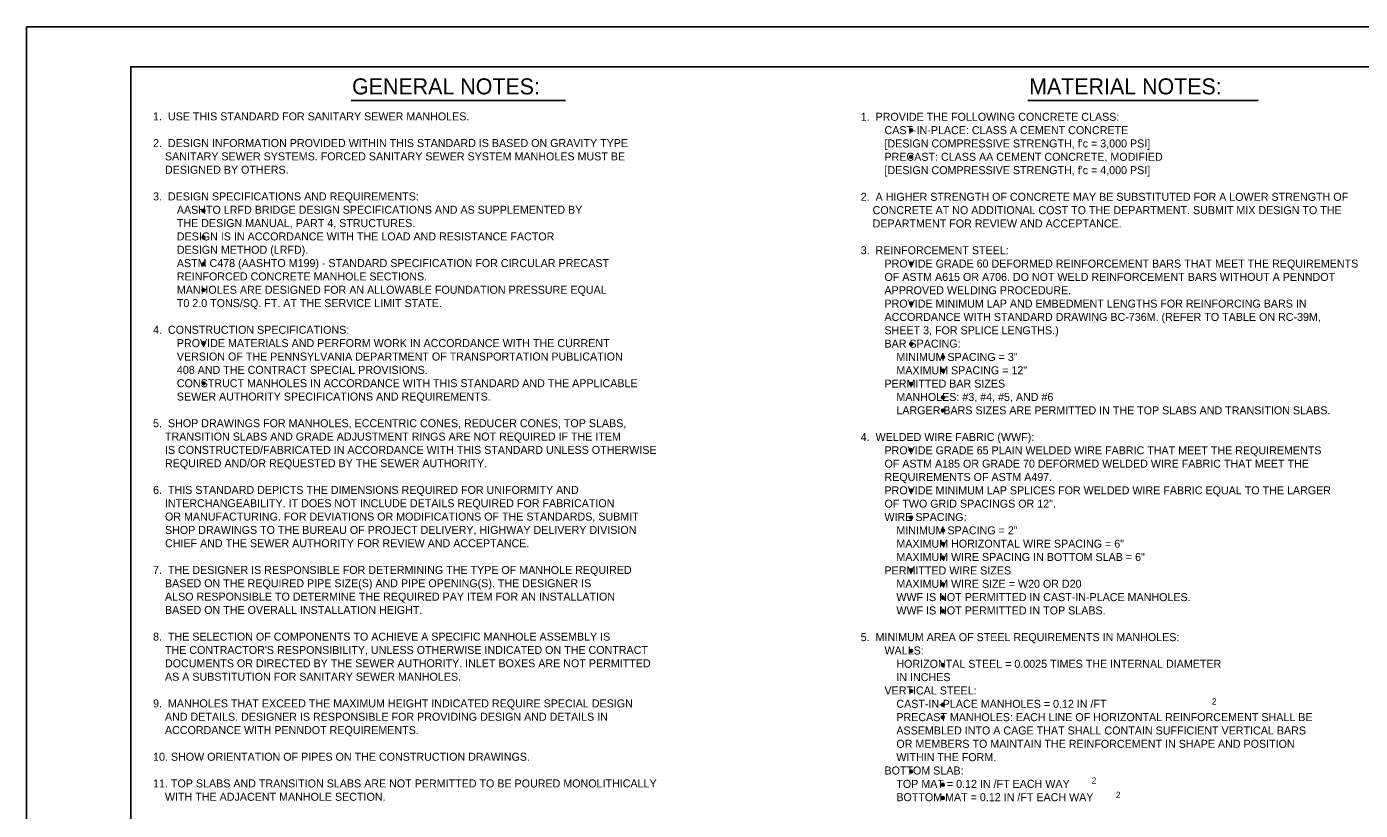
# Model space of a CAD drawing. Extents: x 2106427 to 2114911, y 988717 to 990787.
# Drawn here: x 2106427 to 2108067, y 989824 to 990787 of the extents above; entities that cross this region are included whole.
import ezdxf

# ---------------------------------------------------------------- set-up
doc = ezdxf.new("R2010")
doc.units = 0
for name, color, linetype in [('1', 7, 'Continuous'), ('3', 7, 'Continuous'), ('PLT-BNDY', 7, 'Continuous')]:
    doc.layers.add(name, color=color, linetype=linetype)

msp = doc.modelspace()

# ---------------------------------------------------------------- linework, layer by layer
at = {"layer": '1'}
for p, q in [((2106825.6, 990696.4), (2107089.5, 990696.4)), ((2107657.9, 990696.4), (2107941.3, 990696.4))]:
    msp.add_line(p, q, dxfattribs=at)
msp.add_lwpolyline([(2109133.2, 988887.7), (2109133.2, 990738.1), (2106554.5, 990738.1), (2106554.5, 988887.7), (2109133.2, 988887.7), (2109133.2, 988974.2), (2108477, 988974.2), (2108477, 989186.4), (2109133.2, 989186.4), (2109133.2, 989281.4), (2108477, 989281.4), (2108477, 988887.7), (2108735.6, 988887.7), (2108735.6, 988974.2), (2108735.6, 988887.7), (2108988.2, 988887.7), (2108988.2, 988974.2), (2108988.2, 988933.8), (2109133.2, 988933.8)], dxfattribs=at)
for centre, radius in [((2107514.6, 990659.9), 1.75), ((2107514.6, 990659.9), 1.31), ((2107514.6, 990659.9), 0.875), ((2107514.6, 990659.9), 0.437), ((2107514.6, 990627.2), 1.75), ((2107514.6, 990627.2), 1.31), ((2107514.6, 990627.2), 0.875), ((2107514.6, 990627.2), 0.437), ((2106644, 990561), 1.75), ((2106644, 990561), 1.31), ((2106644, 990561), 0.875), ((2106644, 990561), 0.437), ((2106644, 990528.3), 1.75), ((2106644, 990528.3), 1.31), ((2106644, 990528.3), 0.875), ((2106644, 990528.3), 0.437), ((2106644, 990495.4), 1.75), ((2106644, 990495.4), 1.31), ((2106644, 990495.4), 0.875), ((2106644, 990495.4), 0.437), ((2107514.6, 990496), 1.75), ((2107514.6, 990496), 1.31), ((2107514.6, 990496), 0.875), ((2107514.6, 990496), 0.437), ((2106644, 990463.5), 1.75), ((2106644, 990463.5), 1.31), ((2106644, 990463.5), 0.875), ((2106644, 990463.5), 0.437), ((2107514.6, 990447), 1.75), ((2107514.6, 990447), 1.31), ((2107514.6, 990447), 0.875), ((2107514.6, 990447), 0.437), ((2106644, 990398), 1.75), ((2106644, 990398), 1.31), ((2106644, 990398), 0.875), ((2106644, 990398), 0.437), ((2107514.6, 990397.2), 1.75), ((2107514.6, 990397.2), 1.31), ((2107514.6, 990397.2), 0.875), ((2107514.6, 990397.2), 0.437), ((2107553.7, 990380.8), 1.75), ((2107553.7, 990380.8), 1.31), ((2107553.7, 990380.8), 0.875), ((2107553.7, 990380.8), 0.437), ((2107553.7, 990364.4), 1.75), ((2107553.7, 990364.4), 1.31), ((2107553.7, 990364.4), 0.875), ((2107553.7, 990364.4), 0.437), ((2106644, 990348.8), 1.75), ((2106644, 990348.8), 1.31), ((2106644, 990348.8), 0.875), ((2106644, 990348.8), 0.437), ((2107514.6, 990348), 1.75), ((2107514.6, 990348), 1.31), ((2107514.6, 990348), 0.875), ((2107514.6, 990348), 0.437), ((2107553.7, 990331.5), 1.75), ((2107553.7, 990331.5), 1.31), ((2107553.7, 990331.5), 0.875), ((2107553.7, 990331.5), 0.437), ((2107553.7, 990315.4), 1.75), ((2107553.7, 990315.4), 1.31), ((2107553.7, 990315.4), 0.875), ((2107553.7, 990315.4), 0.437), ((2107513.8, 990266.9), 1.75), ((2107513.8, 990266.9), 1.31), ((2107513.8, 990266.9), 0.875), ((2107513.8, 990266.9), 0.437), ((2107514.6, 990217.1), 1.75), ((2107514.6, 990217.1), 1.31), ((2107514.6, 990217.1), 0.875), ((2107514.6, 990217.1), 0.437), ((2107514.5, 990183.7), 1.75), ((2107514.5, 990183.7), 1.31), ((2107514.5, 990183.7), 0.875), ((2107514.5, 990183.7), 0.437), ((2107553.7, 990168), 1.75), ((2107553.7, 990168), 1.31), ((2107553.7, 990168), 0.875), ((2107553.7, 990168), 0.437), ((2107553.7, 990151.5), 1.75), ((2107553.7, 990151.5), 1.31), ((2107553.7, 990151.5), 0.875), ((2107553.7, 990151.5), 0.437), ((2107553.7, 990134.4), 1.75), ((2107553.7, 990134.4), 1.31), ((2107553.7, 990134.4), 0.875), ((2107553.7, 990134.4), 0.437), ((2107514.5, 990118.9), 1.75), ((2107514.5, 990118.9), 1.31), ((2107514.5, 990118.9), 0.875), ((2107514.5, 990118.9), 0.437), ((2107553.6, 990101.6), 1.75), ((2107553.6, 990101.6), 1.31), ((2107553.6, 990101.6), 0.875), ((2107553.6, 990101.6), 0.437), ((2107553.6, 990085.2), 1.75), ((2107553.6, 990085.2), 1.31), ((2107553.6, 990085.2), 0.875), ((2107553.6, 990085.2), 0.437), ((2107553.6, 990068.5), 1.75), ((2107553.6, 990068.5), 1.31), ((2107553.6, 990068.5), 0.875), ((2107553.6, 990068.5), 0.437), ((2107514.5, 990019.9), 1.75), ((2107514.5, 990019.9), 1.31), ((2107514.5, 990019.9), 0.875), ((2107514.5, 990019.9), 0.437), ((2107553.6, 990002.5), 1.75), ((2107553.6, 990002.5), 1.31), ((2107553.6, 990002.5), 0.875), ((2107553.6, 990002.5), 0.437), ((2107514.5, 989970.2), 1.75), ((2107514.5, 989970.2), 1.31), ((2107514.5, 989970.2), 0.875), ((2107514.5, 989970.2), 0.437), ((2107553.6, 989953.6), 1.75), ((2107553.6, 989953.6), 1.31), ((2107553.6, 989953.6), 0.875), ((2107553.6, 989953.6), 0.437), ((2107553.6, 989938.2), 1.75), ((2107553.6, 989938.2), 1.31), ((2107553.6, 989938.2), 0.875), ((2107553.6, 989938.2), 0.437), ((2107514.5, 989871.4), 1.75), ((2107514.5, 989871.4), 1.31), ((2107514.5, 989871.4), 0.875), ((2107514.5, 989871.4), 0.437), ((2107553.6, 989855.3), 1.75), ((2107553.6, 989855.3), 1.31), ((2107553.6, 989855.3), 0.875), ((2107553.6, 989855.3), 0.437), ((2107553.6, 989838.9), 1.75), ((2107553.6, 989838.9), 1.31), ((2107553.6, 989838.9), 0.875), ((2107553.6, 989838.9), 0.437)]:
    msp.add_circle(centre, radius, dxfattribs=at)
at = {"layer": 'PLT-BNDY'}
msp.add_lwpolyline([(2106426.5, 990787.3), (2109185.7, 990787.3), (2109185.7, 988838.5), (2106426.5, 988838.5)], close=True, dxfattribs=at)

# ---------------------------------------------------------------- texts
at = {"layer": '3'}
for s, height, p in [('GENERAL NOTES:', 19.685, (2106826.8, 990704.1)), ('MATERIAL NOTES:', 19.685, (2107659.7, 990704.1)), ('1.  USE THIS STANDARD FOR SANITARY SEWER MANHOLES.', 9.843, (2106582, 990672.1)), ('1.  PROVIDE THE FOLLOWING CONCRETE CLASS:', 9.843, (2107452.5, 990671.6)), ('        CAST-IN-PLACE: CLASS A CEMENT CONCRETE', 9.843, (2107452.5, 990655.2)), ('2.  DESIGN INFORMATION PROVIDED WITHIN THIS STANDARD IS BASED ON GRAVITY TYPE', 9.843, (2106582, 990639.3)), ("        [DESIGN COMPRESSIVE STRENGTH, f'c = 3,000 PSI]", 9.843, (2107452.5, 990638.8)), ('    SANITARY SEWER SYSTEMS. FORCED SANITARY SEWER SYSTEM MANHOLES MUST BE', 9.843, (2106582, 990622.9)), ('        PRECAST: CLASS AA CEMENT CONCRETE, MODIFIED', 9.843, (2107452.5, 990622.4)), ('    DESIGNED BY OTHERS.', 9.843, (2106582, 990606.5)), ("        [DESIGN COMPRESSIVE STRENGTH, f'c = 4,000 PSI]", 9.843, (2107452.5, 990606)), ('3.  DESIGN SPECIFICATIONS AND REQUIREMENTS:', 9.843, (2106582, 990573.7)), ('2.  A HIGHER STRENGTH OF CONCRETE MAY BE SUBSTITUTED FOR A LOWER STRENGTH OF', 9.843, (2107452.5, 990573.2)), ('        AASHTO LRFD BRIDGE DESIGN SPECIFICATIONS AND AS SUPPLEMENTED BY', 9.843, (2106582, 990557.3)), ('    CONCRETE AT NO ADDITIONAL COST TO THE DEPARTMENT. SUBMIT MIX DESIGN TO THE', 9.843, (2107452.5, 990556.8)), ('        THE DESIGN MANUAL, PART 4, STRUCTURES.', 9.843, (2106582, 990540.9)), ('    DEPARTMENT FOR REVIEW AND ACCEPTANCE.', 9.843, (2107452.5, 990540.4)), ('        DESIGN IS IN ACCORDANCE WITH THE LOAD AND RESISTANCE FACTOR', 9.843, (2106582, 990524.5)), ('        DESIGN METHOD (LRFD).', 9.843, (2106582, 990508.1)), ('3.  REINFORCEMENT STEEL:', 9.843, (2107452.5, 990507.5)), ('        ASTM C478 (AASHTO M199) - STANDARD SPECIFICATION FOR CIRCULAR PRECAST', 9.843, (2106582, 990491.7)), ('        PROVIDE GRADE 60 DEFORMED REINFORCEMENT BARS THAT MEET THE REQUIREMENTS', 9.843, (2107452.5, 990491.1)), ('        REINFORCED CONCRETE MANHOLE SECTIONS.', 9.843, (2106582, 990475.3)), ('        OF ASTM A615 OR A706. DO NOT WELD REINFORCEMENT BARS WITHOUT A PENNDOT', 9.843, (2107452.5, 990474.7)), ('        MANHOLES ARE DESIGNED FOR AN ALLOWABLE FOUNDATION PRESSURE EQUAL', 9.843, (2106582, 990458.9)), ('        APPROVED WELDING PROCEDURE.', 9.843, (2107452.5, 990458.3)), ('        T0 2.0 TONS/SQ. FT. AT THE SERVICE LIMIT STATE.', 9.843, (2106582, 990442.5)), ('        PROVIDE MINIMUM LAP AND EMBEDMENT LENGTHS FOR REINFORCING BARS IN ', 9.843, (2107452.5, 990441.9)), ('        ACCORDANCE WITH STANDARD DRAWING BC-736M. (REFER TO TABLE ON RC-39M,', 9.843, (2107452.5, 990425.5)), ('4.  CONSTRUCTION SPECIFICATIONS:', 9.843, (2106582, 990409.7)), ('        SHEET 3, FOR SPLICE LENGTHS.)', 9.843, (2107452.5, 990409.1)), ('        PROVIDE MATERIALS AND PERFORM WORK IN ACCORDANCE WITH THE CURRENT', 9.843, (2106582, 990393.3)), ('        BAR SPACING:', 9.843, (2107452.5, 990392.7)), ('        VERSION OF THE PENNSYLVANIA DEPARTMENT OF TRANSPORTATION PUBLICATION', 9.843, (2106582, 990376.8)), ('            MINIMUM SPACING = 3"', 9.843, (2107452.5, 990376.3)), ('        408 AND THE CONTRACT SPECIAL PROVISIONS.', 9.843, (2106582, 990360.4)), ('            MAXIMUM SPACING = 12"', 9.843, (2107452.5, 990359.9)), ('        CONSTRUCT MANHOLES IN ACCORDANCE WITH THIS STANDARD AND THE APPLICABLE', 9.843, (2106582, 990344)), ('        PERMITTED BAR SIZES', 9.843, (2107452.5, 990343.5)), ('        SEWER AUTHORITY SPECIFICATIONS AND REQUIREMENTS.', 9.843, (2106582, 990327.6)), ('            MANHOLES: #3, #4, #5, AND #6', 9.843, (2107452.5, 990327.1)), ('            LARGER BARS SIZES ARE PERMITTED IN THE TOP SLABS AND TRANSITION SLABS.', 9.843, (2107452.5, 990310.7)), ('5.  SHOP DRAWINGS FOR MANHOLES, ECCENTRIC CONES, REDUCER CONES, TOP SLABS,', 9.843, (2106582, 990294.8)), ('    TRANSITION SLABS AND GRADE ADJUSTMENT RINGS ARE NOT REQUIRED IF THE ITEM', 9.843, (2106582, 990278.4)), ('4.  WELDED WIRE FABRIC (WWF):', 9.843, (2107452.5, 990277.9)), ('    IS CONSTRUCTED/FABRICATED IN ACCORDANCE WITH THIS STANDARD UNLESS OTHERWISE', 9.843, (2106582, 990262)), ('        PROVIDE GRADE 65 PLAIN WELDED WIRE FABRIC THAT MEET THE REQUIREMENTS', 9.843, (2107452.5, 990261.5)), ('    REQUIRED AND/OR REQUESTED BY THE SEWER AUTHORITY.', 9.843, (2106582, 990245.6)), ('        OF ASTM A185 OR GRADE 70 DEFORMED WELDED WIRE FABRIC THAT MEET THE', 9.843, (2107452.5, 990245.1)), ('        REQUIREMENTS OF ASTM A497.', 9.843, (2107452.5, 990228.7)), ('6.  THIS STANDARD DEPICTS THE DIMENSIONS REQUIRED FOR UNIFORMITY AND', 9.843, (2106582, 990212.8)), ('        PROVIDE MINIMUM LAP SPLICES FOR WELDED WIRE FABRIC EQUAL TO THE LARGER', 9.843, (2107452.5, 990212.3)), ('    INTERCHANGEABILITY. IT DOES NOT INCLUDE DETAILS REQUIRED FOR FABRICATION', 9.843, (2106582, 990196.4)), ('        OF TWO GRID SPACINGS OR 12".', 9.843, (2107452.5, 990195.9)), ('    OR MANUFACTURING. FOR DEVIATIONS OR MODIFICATIONS OF THE STANDARDS, SUBMIT', 9.843, (2106582, 990180)), ('        WIRE SPACING:', 9.843, (2107452.5, 990179.5)), ('    SHOP DRAWINGS TO THE BUREAU OF PROJECT DELIVERY, HIGHWAY DELIVERY DIVISION', 9.843, (2106582, 990163.6)), ('            MINIMUM SPACING = 2"', 9.843, (2107452.5, 990163.1)), ('    CHIEF AND THE SEWER AUTHORITY FOR REVIEW AND ACCEPTANCE.', 9.843, (2106582, 990147.2)), ('            MAXIMUM HORIZONTAL WIRE SPACING = 6" ', 9.843, (2107452.5, 990146.7)), ('            MAXIMUM WIRE SPACING IN BOTTOM SLAB = 6"', 9.843, (2107452.5, 990130.3)), ('7.  THE DESIGNER IS RESPONSIBLE FOR DETERMINING THE TYPE OF MANHOLE REQUIRED', 9.843, (2106582, 990114.4)), ('        PERMITTED WIRE SIZES', 9.843, (2107452.5, 990113.8)), ('    BASED ON THE REQUIRED PIPE SIZE(S) AND PIPE OPENING(S). THE DESIGNER IS', 9.843, (2106582, 990098)), ('            MAXIMUM WIRE SIZE = W20 OR D20', 9.843, (2107452.5, 990097.4)), ('    ALSO RESPONSIBLE TO DETERMINE THE REQUIRED PAY ITEM FOR AN INSTALLATION', 9.843, (2106582, 990081.6)), ('            WWF IS NOT PERMITTED IN CAST-IN-PLACE MANHOLES.', 9.843, (2107452.5, 990081)), ('    BASED ON THE OVERALL INSTALLATION HEIGHT.', 9.843, (2106582, 990065.2)), ('            WWF IS NOT PERMITTED IN TOP SLABS.', 9.843, (2107452.5, 990064.6)), ('8.  THE SELECTION OF COMPONENTS TO ACHIEVE A SPECIFIC MANHOLE ASSEMBLY IS', 9.843, (2106582, 990032.4)), ('5.  MINIMUM AREA OF STEEL REQUIREMENTS IN MANHOLES:', 9.843, (2107452.5, 990031.8)), ("    THE CONTRACTOR'S RESPONSIBILITY, UNLESS OTHERWISE INDICATED ON THE CONTRACT", 9.843, (2106582, 990016)), ('        WALLS:', 9.843, (2107452.5, 990015.4)), ('    DOCUMENTS OR DIRECTED BY THE SEWER AUTHORITY. INLET BOXES ARE NOT PERMITTED', 9.843, (2106582, 989999.6)), ('            HORIZONTAL STEEL = 0.0025 TIMES THE INTERNAL DIAMETER', 9.843, (2107452.5, 989999)), ('    AS A SUBSTITUTION FOR SANITARY SEWER MANHOLES.', 9.843, (2106582, 989983.1)), ('            IN INCHES', 9.843, (2107452.5, 989982.6)), ('        VERTICAL STEEL:', 9.843, (2107452.5, 989966.2)), ('9.  MANHOLES THAT EXCEED THE MAXIMUM HEIGHT INDICATED REQUIRE SPECIAL DESIGN', 9.843, (2106582, 989950.3)), ('            CAST-IN-PLACE MANHOLES = 0.12 IN /FT', 9.843, (2107452.5, 989949.8)), ('2', 7.5, (2107884.6, 989953.8)), ('    AND DETAILS. DESIGNER IS RESPONSIBLE FOR PROVIDING DESIGN AND DETAILS IN', 9.843, (2106582, 989933.9)), ('            PRECAST MANHOLES: EACH LINE OF HORIZONTAL REINFORCEMENT SHALL BE', 9.843, (2107452.5, 989933.4)), ('    ACCORDANCE WITH PENNDOT REQUIREMENTS.', 9.843, (2106582, 989917.5)), ('            ASSEMBLED INTO A CAGE THAT SHALL CONTAIN SUFFICIENT VERTICAL BARS', 9.843, (2107452.5, 989917)), ('            OR MEMBERS TO MAINTAIN THE REINFORCEMENT IN SHAPE AND POSITION', 9.843, (2107452.5, 989900.6)), ('10. SHOW ORIENTATION OF PIPES ON THE CONSTRUCTION DRAWINGS.', 9.843, (2106582, 989884.7)), ('            WITHIN THE FORM.', 9.843, (2107452.5, 989884.2)), ('        BOTTOM SLAB:', 9.843, (2107452.5, 989867.8)), ('11. TOP SLABS AND TRANSITION SLABS ARE NOT PERMITTED TO BE POURED MONOLITHICALLY', 9.843, (2106582, 989851.9)), ('            TOP MAT = 0.12 IN /FT EACH WAY', 9.843, (2107452.5, 989851.4)), ('2', 7.5, (2107736.7, 989856.7)), ('    WITH THE ADJACENT MANHOLE SECTION.', 9.843, (2106582, 989835.5)), ('            BOTTOM MAT = 0.12 IN /FT EACH WAY', 9.843, (2107452.5, 989835)), ('2', 7.5, (2107766.5, 989839.1))]:
    msp.add_text(s, height=height, dxfattribs=at).set_placement(p)

doc.saveas('drawing.dxf')
